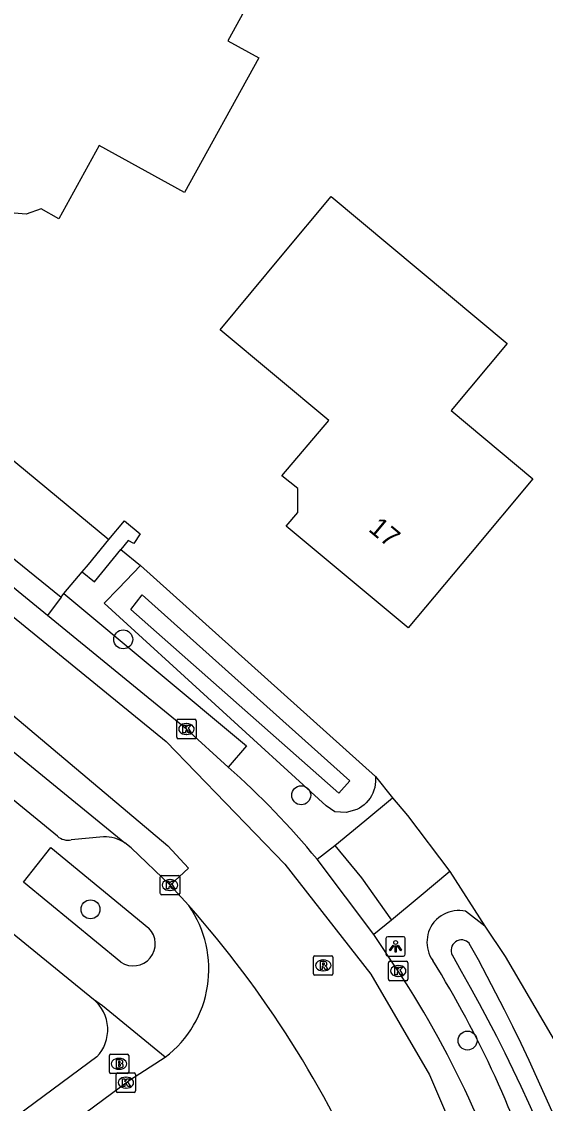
# Model space of a CAD drawing. Extents: x 163427 to 164190, y 380331 to 381641.
# Drawn here: x 163893.8 to 163920.8, y 381365.1 to 381420.9 of the extents above; entities that cross this region are included whole.
import ezdxf

# ---------------------------------------------------------------- set-up
doc = ezdxf.new("R2010")
doc.units = 0
for name, color, linetype in [('IMGEO_Boom', 7, 'Continuous'), ('IMGEO_Brandkraan', 7, 'Continuous'), ('IMGEO_Erf', 7, 'Continuous'), ('IMGEO_Groenvoorziening', 7, 'Continuous'), ('IMGEO_Haag', 7, 'Continuous'), ('IMGEO_Kolk', 7, 'Continuous'), ('IMGEO_Lichtpunt', 7, 'Continuous'), ('IMGEO_Pand', 7, 'Continuous'), ('IMGEO_Pand_nummerreeks', 7, 'Continuous'), ('IMGEO_Rijbaan_lokaal_gesloten', 7, 'Continuous'), ('IMGEO_Rijbaan_lokaal_open', 7, 'Continuous'), ('IMGEO_Rioolput', 7, 'Continuous'), ('IMGEO_Voetpad_open', 7, 'Continuous'), ('IMGEO_Waterloop', 7, 'Continuous')]:
    doc.layers.add(name, color=color, linetype=linetype)

msp = doc.modelspace()

# ---------------------------------------------------------------- linework, layer by layer
at = {"layer": 'IMGEO_Boom'}
for centre in [(163899.055, 381389.033), (163908.244, 381380.996), (163897.368, 381375.115), (163916.827, 381368.349)]:
    msp.add_circle(centre, 0.489, dxfattribs=at)
at = {"layer": 'IMGEO_Brandkraan'}
for p, q in [((163898.34, 381366.723), (163898.34, 381367.575)), ((163898.415, 381367.649), (163899.267, 381367.649)), ((163898.828, 381367.429), (163898.853, 381367.429)), ((163899.341, 381367.575), (163899.341, 381366.723)), ((163898.851, 381366.869), (163898.826, 381366.869)), ((163899.267, 381366.649), (163898.415, 381366.649))]:
    msp.add_line(p, q, dxfattribs=at)
for points in [[(163898.34, 381366.723), (163898.34, 381367.575)], [(163898.415, 381367.649), (163899.267, 381367.649)], [(163898.688, 381367.349), (163898.688, 381366.949), (163898.901, 381366.949)], [(163898.919, 381367.349), (163898.688, 381367.349)], [(163899.341, 381367.575), (163899.341, 381366.723)], [(163898.867, 381367.268), (163898.813, 381367.268), (163898.813, 381367.192)], [(163898.813, 381367.192), (163898.866, 381367.192)], [(163898.875, 381367.116), (163898.813, 381367.116), (163898.813, 381367.035)], [(163898.813, 381367.035), (163898.875, 381367.035)], [(163899.267, 381366.649), (163898.415, 381366.649)]]:
    msp.add_lwpolyline(points, dxfattribs=at)
for centre, radius, start, end in [((163898.417, 381367.573), 0.0765, 91.552, 178.448), ((163898.417, 381367.573), 0.0765, 91.552, 178.448), ((163898.923, 381367.204), 0.145, 59.4692, 91.5367), ((163898.948, 381367.251), 0.0922, 285.5137, 58.1501), ((163899.265, 381367.573), 0.0765, 1.552, 88.448), ((163899.265, 381367.573), 0.0765, 1.552, 88.448), ((163898.868, 381367.23), 0.0379, 267.8285, 90.9355), ((163898.876, 381367.075), 0.0404, 269.8759, 90.5077), ((163898.907, 381367.2), 0.251, 268.6676, 293.5347), ((163898.953, 381367.059), 0.105, 301.3115, 78.989), ((163898.417, 381366.725), 0.0765, 181.552, 268.448), ((163898.417, 381366.725), 0.0765, 181.552, 268.448), ((163899.265, 381366.725), 0.0765, 271.552, 358.448), ((163899.265, 381366.725), 0.0765, 271.552, 358.448)]:
    msp.add_arc(centre, radius, start, end, dxfattribs=at)
for centre, major_axis, ratio, start_param, end_param in [((163898.827, 381367.149), (-0.387, 0.002), 0.722429, 4.712389, 7.853982), ((163898.852, 381367.149), (-0.39, 0.002), 0.717154, 1.570796, 4.712389)]:
    msp.add_ellipse(centre, major_axis=major_axis, ratio=ratio, start_param=start_param, end_param=end_param, dxfattribs=at)
at = {"layer": 'IMGEO_Erf'}
for points in [[(163899.94, 381392.847), (163912.076, 381381.957)], [(163917.715, 381374.256), (163918.762, 381372.692), (163921.534, 381367.958), (163923.872, 381362.995), (163925.758, 381357.843), (163928.758, 381344.373)]]:
    msp.add_lwpolyline(points, dxfattribs=at)
at = {"layer": 'IMGEO_Groenvoorziening'}
for points in [[(163898.941, 381393.671), (163899.94, 381392.847)], [(163912.076, 381381.957), (163912.083, 381381.851), (163912.081, 381381.699), (163912.065, 381381.548), (163912.036, 381381.399), (163911.994, 381381.252), (163911.939, 381381.111), (163911.871, 381380.974), (163911.792, 381380.845), (163911.701, 381380.723), (163911.6, 381380.609), (163911.489, 381380.505), (163911.369, 381380.411), (163911.242, 381380.329), (163911.107, 381380.258), (163910.555, 381380.105), (163909.984, 381380.144), (163909.522, 381380.45), (163898.08, 381390.895), (163898.806, 381391.656), (163899.94, 381392.847)], [(163912.076, 381381.957), (163912.961, 381380.857)], [(163915.906, 381377.066), (163917.715, 381374.256)], [(163917.715, 381374.256), (163916.719, 381375.016), (163916.575, 381375.041), (163916.429, 381375.053), (163916.283, 381375.052), (163916.137, 381375.038), (163915.993, 381375.012), (163915.852, 381374.972), (163915.716, 381374.92), (163915.584, 381374.856), (163915.459, 381374.78), (163915.341, 381374.694), (163915.231, 381374.597), (163915.189, 381374.555)]]:
    msp.add_lwpolyline(points, dxfattribs=at)
for centre, radius, start, end in [((163916.366, 381373.419), 1.636, 136.0192, 215.297), ((163869.721, 381344.268), 53.372, 17.3163, 31.9027)]:
    msp.add_arc(centre, radius, start, end, dxfattribs=at)
at = {"layer": 'IMGEO_Haag'}
for points in [[(163898.316, 381394.186), (163899.12, 381395.141), (163899.928, 381394.467), (163899.6, 381393.981), (163899.319, 381394.133), (163898.941, 381393.671)], [(163896.942, 381392.508), (163897.571, 381391.999), (163898.941, 381393.671)]]:
    msp.add_lwpolyline(points, dxfattribs=at)
at = {"layer": 'IMGEO_Kolk'}
for p, q in [((163901.82, 381383.985), (163901.82, 381384.837)), ((163901.895, 381384.911), (163902.747, 381384.911)), ((163902.308, 381384.691), (163902.333, 381384.691)), ((163902.821, 381384.837), (163902.821, 381383.985)), ((163902.331, 381384.131), (163902.306, 381384.131)), ((163902.747, 381383.911), (163901.895, 381383.911)), ((163900.971, 381375.94), (163900.971, 381376.792)), ((163901.046, 381376.866), (163901.898, 381376.866)), ((163901.972, 381376.792), (163901.972, 381375.94)), ((163901.459, 381376.646), (163901.484, 381376.646)), ((163901.898, 381375.866), (163901.046, 381375.866)), ((163901.482, 381376.086), (163901.457, 381376.086)), ((163912.747, 381371.511), (163912.747, 381372.363)), ((163912.822, 381372.437), (163913.674, 381372.437)), ((163913.748, 381372.363), (163913.748, 381371.511)), ((163913.235, 381372.217), (163913.26, 381372.217)), ((163913.674, 381371.437), (163912.822, 381371.437)), ((163913.258, 381371.657), (163913.233, 381371.657)), ((163898.693, 381365.754), (163898.693, 381366.606)), ((163898.768, 381366.68), (163899.62, 381366.68)), ((163899.181, 381366.46), (163899.206, 381366.46)), ((163899.694, 381366.606), (163899.694, 381365.754)), ((163899.62, 381365.68), (163898.768, 381365.68)), ((163899.204, 381365.9), (163899.179, 381365.9))]:
    msp.add_line(p, q, dxfattribs=at)
for points in [[(163901.82, 381383.985), (163901.82, 381384.837)], [(163901.895, 381384.911), (163902.747, 381384.911)], [(163902.141, 381384.611), (163902.264, 381384.611), (163902.264, 381384.46), (163902.394, 381384.611), (163902.558, 381384.611), (163902.412, 381384.46), (163902.565, 381384.211), (163902.413, 381384.211), (163902.328, 381384.375), (163902.264, 381384.308), (163902.264, 381384.211), (163902.141, 381384.211), (163902.141, 381384.611)], [(163902.821, 381384.837), (163902.821, 381383.985)], [(163902.747, 381383.911), (163901.895, 381383.911)], [(163900.971, 381375.94), (163900.971, 381376.792)], [(163901.046, 381376.866), (163901.898, 381376.866)], [(163901.972, 381376.792), (163901.972, 381375.94)], [(163901.292, 381376.566), (163901.415, 381376.566), (163901.415, 381376.415), (163901.545, 381376.566), (163901.709, 381376.566), (163901.563, 381376.415), (163901.716, 381376.166), (163901.564, 381376.166), (163901.479, 381376.33), (163901.415, 381376.263), (163901.415, 381376.166), (163901.292, 381376.166), (163901.292, 381376.566)], [(163901.898, 381375.866), (163901.046, 381375.866)], [(163912.747, 381371.511), (163912.747, 381372.363)], [(163912.822, 381372.437), (163913.674, 381372.437)], [(163913.748, 381372.363), (163913.748, 381371.511)], [(163913.068, 381372.137), (163913.191, 381372.137), (163913.191, 381371.986), (163913.321, 381372.137), (163913.485, 381372.137), (163913.339, 381371.986), (163913.492, 381371.737), (163913.34, 381371.737), (163913.255, 381371.901), (163913.191, 381371.834), (163913.191, 381371.737), (163913.068, 381371.737), (163913.068, 381372.137)], [(163913.674, 381371.437), (163912.822, 381371.437)], [(163898.693, 381365.754), (163898.693, 381366.606)], [(163898.768, 381366.68), (163899.62, 381366.68)], [(163899.014, 381366.38), (163899.137, 381366.38), (163899.137, 381366.229), (163899.267, 381366.38), (163899.431, 381366.38), (163899.285, 381366.229), (163899.438, 381365.98), (163899.286, 381365.98), (163899.201, 381366.144), (163899.137, 381366.077), (163899.137, 381365.98), (163899.014, 381365.98), (163899.014, 381366.38)], [(163899.694, 381366.606), (163899.694, 381365.754)], [(163899.62, 381365.68), (163898.768, 381365.68)]]:
    msp.add_lwpolyline(points, dxfattribs=at)
for centre, start, end in [((163901.897, 381384.835), 91.552, 178.448), ((163901.897, 381384.835), 91.552, 178.448), ((163902.745, 381384.835), 1.552, 88.448), ((163902.745, 381384.835), 1.552, 88.448), ((163901.897, 381383.987), 181.552, 268.448), ((163901.897, 381383.987), 181.552, 268.448), ((163902.745, 381383.987), 271.552, 358.448), ((163902.745, 381383.987), 271.552, 358.448), ((163901.048, 381376.79), 91.552, 178.448), ((163901.048, 381376.79), 91.552, 178.448), ((163901.896, 381376.79), 1.552, 88.448), ((163901.896, 381376.79), 1.552, 88.448), ((163901.048, 381375.942), 181.552, 268.448), ((163901.048, 381375.942), 181.552, 268.448), ((163901.896, 381375.942), 271.552, 358.448), ((163901.896, 381375.942), 271.552, 358.448), ((163912.824, 381372.361), 91.552, 178.448), ((163912.824, 381372.361), 91.552, 178.448), ((163913.672, 381372.361), 1.552, 88.448), ((163913.672, 381372.361), 1.552, 88.448), ((163912.824, 381371.513), 181.552, 268.448), ((163912.824, 381371.513), 181.552, 268.448), ((163913.672, 381371.513), 271.552, 358.448), ((163913.672, 381371.513), 271.552, 358.448), ((163898.77, 381366.604), 91.552, 178.448), ((163898.77, 381366.604), 91.552, 178.448), ((163899.618, 381366.604), 1.552, 88.448), ((163899.618, 381366.604), 1.552, 88.448), ((163898.77, 381365.756), 181.552, 268.448), ((163898.77, 381365.756), 181.552, 268.448), ((163899.618, 381365.756), 271.552, 358.448), ((163899.618, 381365.756), 271.552, 358.448)]:
    msp.add_arc(centre, 0.0765, start, end, dxfattribs=at)
for centre, major_axis, ratio, start_param, end_param in [((163902.307, 381384.411), (-0.387, 0.002), 0.722429, 4.712389, 7.853982), ((163902.332, 381384.411), (-0.39, 0.002), 0.717154, 1.570796, 4.712389), ((163901.458, 381376.366), (-0.387, 0.002), 0.722429, 4.712389, 7.853982), ((163901.483, 381376.366), (-0.39, 0.002), 0.717154, 1.570796, 4.712389), ((163913.234, 381371.937), (-0.387, 0.002), 0.722429, 4.712389, 7.853982), ((163913.259, 381371.937), (-0.39, 0.002), 0.717154, 1.570796, 4.712389), ((163899.18, 381366.18), (-0.387, 0.002), 0.722429, 4.712389, 7.853982), ((163899.205, 381366.18), (-0.39, 0.002), 0.717154, 1.570796, 4.712389)]:
    msp.add_ellipse(centre, major_axis=major_axis, ratio=ratio, start_param=start_param, end_param=end_param, dxfattribs=at)
at = {"layer": 'IMGEO_Lichtpunt'}
for p, q in [((163912.614, 381373.61), (163912.614, 381372.803)), ((163912.614, 381373.61), (163912.614, 381372.803)), ((163913.516, 381373.705), (163912.708, 381373.705)), ((163913.516, 381373.705), (163912.708, 381373.705)), ((163913.61, 381372.803), (163913.61, 381373.61)), ((163913.61, 381372.803), (163913.61, 381373.61)), ((163912.708, 381372.709), (163913.516, 381372.709)), ((163912.708, 381372.709), (163913.516, 381372.709))]:
    msp.add_line(p, q, dxfattribs=at)
for points in [[(163912.988, 381373.274), (163913.027, 381373.246), (163912.839, 381372.984), (163912.801, 381373.011), (163912.988, 381373.274)], [(163913.09, 381373.226), (163913.137, 381373.226), (163913.137, 381372.904), (163913.09, 381372.904), (163913.09, 381373.226)], [(163913.2, 381373.246), (163913.238, 381373.273), (163913.425, 381373.011), (163913.386, 381372.983), (163913.2, 381373.246)]]:
    msp.add_lwpolyline(points, dxfattribs=at)
msp.add_circle((163913.113, 381373.408), 0.0994, dxfattribs=at)
for centre, start, end in [((163912.708, 381373.61), 90, 180), ((163912.708, 381373.61), 90, 180), ((163913.516, 381373.61), 0, 90), ((163913.516, 381373.61), 0, 90), ((163912.708, 381372.803), 180, 270), ((163912.708, 381372.803), 180, 270), ((163913.516, 381372.803), 270, 0), ((163913.516, 381372.803), 270, 360)]:
    msp.add_arc(centre, 0.0946, start, end, dxfattribs=at)
at = {"layer": 'IMGEO_Pand'}
for points in [[(163902.213, 381412.064), (163897.812, 381414.49), (163895.741, 381410.721), (163894.829, 381411.224), (163894.04, 381410.957), (163893.215, 381411.027), (163892.475, 381411.43), (163891.961, 381412.085), (163891.751, 381412.88), (163890.835, 381413.398), (163892.849, 381416.261), (163887.994, 381418.971), (163884.698, 381414.489), (163880.997, 381417.224), (163889.175, 381428.294), (163894.787, 381425.22), (163896.627, 381428.557), (163903.405, 381424.818), (163902.414, 381423.022), (163905.303, 381421.428), (163904.457, 381419.895), (163906.048, 381419.017), (163902.213, 381412.064)], [(163918.864, 381404.287), (163915.975, 381400.833), (163920.196, 381397.302), (163916.978, 381393.455), (163913.769, 381389.62), (163907.462, 381394.87), (163908.07, 381395.57), (163908.062, 381396.806), (163907.248, 381397.463), (163909.666, 381400.316), (163904.056, 381404.997), (163907.261, 381408.835), (163909.79, 381411.864), (163918.864, 381404.287)]]:
    msp.add_lwpolyline(points, dxfattribs=at)
at = {"layer": 'IMGEO_Rijbaan_lokaal_gesloten'}
for points in [[(163712.408, 381497.746), (163724.81, 381492.736), (163743.644, 381483.934), (163766.443, 381472.53), (163780.444, 381464.999), (163785.277, 381462.271), (163803.377, 381451.63), (163810.77, 381447.112), (163827.662, 381436.066), (163844.931, 381423.887), (163862.01, 381410.858), (163868.144, 381405.949), (163877.464, 381398.208), (163891.264, 381386.878), (163901.361, 381378.381), (163902.433, 381377.241), (163901.472, 381376.366)], [(163841.848, 381430.533), (163854.116, 381421.564), (163876.198, 381404.193), (163879.891, 381401.183), (163901.267, 381383.762), (163907.4, 381377.437), (163911.836, 381371.772), (163914.855, 381366.58), (163916.89, 381361.86), (163918.27, 381356.954), (163928.731, 381319.775), (163929.065, 381319.87), (163929.681, 381317.703), (163929.322, 381317.601), (163935.871, 381293.48), (163936.342, 381291.876), (163937.807, 381292.203)], [(163849.426, 381418.607), (163856.415, 381413.258), (163861.726, 381409.101), (163899.144, 381378.545)], [(163895.146, 381390.26), (163888.681, 381395.546)], [(163904.472, 381382.452), (163902.32, 381384.41), (163895.146, 381390.26)], [(163901.472, 381376.366), (163899.466, 381378.282), (163899.144, 381378.545)], [(163911.984, 381373.814), (163909.062, 381377.697)], [(163902.435, 381375.31), (163901.472, 381376.366)], [(163913.247, 381371.936), (163911.984, 381373.814)]]:
    msp.add_lwpolyline(points, dxfattribs=at)
for centre, radius, start, end in [((163876.542, 381350.898), 42.139, 39.4908, 48.4861), ((163861.382, 381338.888), 54.881, 23.2004, 41.5796), ((163870.916, 381344.1), 50.663, 15.2029, 33.3278)]:
    msp.add_arc(centre, radius, start, end, dxfattribs=at)
at = {"layer": 'IMGEO_Rijbaan_lokaal_open'}
for points in [[(163895.852, 381391.216), (163895.999, 381391.394)], [(163895.999, 381391.394), (163905.423, 381383.55), (163904.472, 381382.452)], [(163895.852, 381391.216), (163895.146, 381390.26)], [(163853.339, 381332.241), (163853.766, 381332.578), (163899.382, 381366.301), (163901.215, 381367.486)]]:
    msp.add_lwpolyline(points, dxfattribs=at)
msp.add_arc((163897.772, 381372.03), 5.701, 307.1525, 35.1219, dxfattribs=at)
at = {"layer": 'IMGEO_Rioolput'}
for p, q in [((163908.877, 381371.798), (163908.877, 381372.65)), ((163908.952, 381372.724), (163909.804, 381372.724)), ((163909.365, 381372.504), (163909.39, 381372.504)), ((163909.878, 381372.65), (163909.878, 381371.798)), ((163909.388, 381371.944), (163909.363, 381371.944)), ((163909.804, 381371.724), (163908.952, 381371.724))]:
    msp.add_line(p, q, dxfattribs=at)
for points in [[(163908.877, 381371.798), (163908.877, 381372.65)], [(163908.952, 381372.724), (163909.804, 381372.724)], [(163909.466, 381372.422), (163909.214, 381372.424), (163909.214, 381372.024)], [(163909.392, 381372.343), (163909.338, 381372.343), (163909.338, 381372.262)], [(163909.878, 381372.65), (163909.878, 381371.798)], [(163909.214, 381372.024), (163909.338, 381372.024), (163909.338, 381372.186), (163909.349, 381372.186)], [(163909.338, 381372.262), (163909.39, 381372.262)], [(163909.396, 381372.157), (163909.467, 381372.024), (163909.607, 381372.024), (163909.542, 381372.15)], [(163909.804, 381371.724), (163908.952, 381371.724)]]:
    msp.add_lwpolyline(points, dxfattribs=at)
for centre, radius, start, end in [((163908.954, 381372.648), 0.0765, 91.552, 178.448), ((163908.954, 381372.648), 0.0765, 91.552, 178.448), ((163909.398, 381372.247), 0.0964, 77.0061, 93.1865), ((163909.412, 381372.304), 0.0378, 276.6634, 79.6772), ((163909.465, 381372.312), 0.109, 350.3612, 89.416), ((163909.802, 381372.648), 0.0765, 1.552, 88.448), ((163909.802, 381372.648), 0.0765, 1.552, 88.448), ((163908.954, 381371.8), 0.0765, 181.552, 268.448), ((163908.954, 381371.8), 0.0765, 181.552, 268.448), ((163909.348, 381372.133), 0.0533, 26.0293, 88.6989), ((163909.374, 381372.451), 0.19, 274.7715, 282.9687), ((163909.463, 381372.312), 0.112, 277.5842, 350.9817), ((163909.447, 381372.097), 0.108, 29.5134, 73.7905), ((163909.802, 381371.8), 0.0765, 271.552, 358.448), ((163909.802, 381371.8), 0.0765, 271.552, 358.448)]:
    msp.add_arc(centre, radius, start, end, dxfattribs=at)
for centre, major_axis, ratio, start_param, end_param in [((163909.364, 381372.224), (-0.387, 0.002), 0.722429, 4.712389, 7.853982), ((163909.389, 381372.224), (-0.39, 0.002), 0.717154, 1.570796, 4.712389)]:
    msp.add_ellipse(centre, major_axis=major_axis, ratio=ratio, start_param=start_param, end_param=end_param, dxfattribs=at)
at = {"layer": 'IMGEO_Voetpad_open'}
for points in [[(163897.514, 381370.475), (163857.324, 381403.21), (163851.227, 381407.961), (163844.818, 381412.831), (163838.787, 381417.275)], [(163895.666, 381378.887), (163891.555, 381382.236), (163887.861, 381385.245), (163883.753, 381388.592), (163880.438, 381391.293), (163876.32, 381394.648), (163872.424, 381397.808), (163871.394, 381398.618), (163868.294, 381401.138), (163864.399, 381404.304), (163860.286, 381407.648), (163856.343, 381410.772), (163852.14, 381413.991), (163851.342, 381414.59), (163850.543, 381415.186)], [(163891.905, 381399.473), (163898.316, 381394.186)], [(163889.4, 381396.416), (163895.852, 381391.216)], [(163896.942, 381392.508), (163897.273, 381392.9), (163898.316, 381394.186)], [(163895.999, 381391.394), (163896.942, 381392.508)], [(163909.974, 381378.398), (163911.517, 381379.686), (163912.961, 381380.857)], [(163912.961, 381380.857), (163913.73, 381379.954), (163915.906, 381377.066)], [(163898.042, 381378.845), (163896.378, 381378.705)], [(163898.937, 381372.39), (163893.903, 381376.52), (163895.319, 381378.307)], [(163895.319, 381378.307), (163900.385, 381374.147)], [(163909.062, 381377.697), (163909.974, 381378.398)], [(163909.974, 381378.398), (163911.354, 381376.74), (163912.902, 381374.55)], [(163915.906, 381377.066), (163914.334, 381375.749), (163912.902, 381374.55)], [(163912.902, 381374.55), (163911.984, 381373.814)], [(163901.215, 381367.486), (163897.986, 381370.139), (163897.514, 381370.475)], [(163897.686, 381367.504), (163854.312, 381335.419), (163850.881, 381332.872)]]:
    msp.add_lwpolyline(points, dxfattribs=at)
for centre, radius, start, end in [((163896.195, 381379.471), 0.788, 227.855, 283.4674), ((163898.124, 381376.971), 1.876, 57.0502, 92.4924), ((163899.57, 381373.343), 1.144, 236.4075, 44.6064), ((163896.24, 381368.911), 2.018, 315.7911, 50.8355)]:
    msp.add_arc(centre, radius, start, end, dxfattribs=at)
at = {"layer": 'IMGEO_Waterloop'}
msp.add_lwpolyline([(163899.445, 381390.574), (163900.04, 381391.334), (163910.745, 381381.733), (163910.184, 381381.108), (163899.445, 381390.574)], dxfattribs=at)
for centre, radius, start, end in [((163916.511, 381373.003), 0.536, 40.5464, 208.5924), ((163834.42, 381327.311), 94.475, 10.42804, 29.1648), ((163841.503, 381329.282), 86.284, 9.97217, 30.24706)]:
    msp.add_arc(centre, radius, start, end, dxfattribs=at)

# ---------------------------------------------------------------- texts
at = {"layer": 'IMGEO_Pand_nummerreeks'}
msp.add_text('17', height=1, rotation=320.2257, dxfattribs=at).set_placement((163911.663, 381394.653))

doc.saveas('drawing.dxf')
